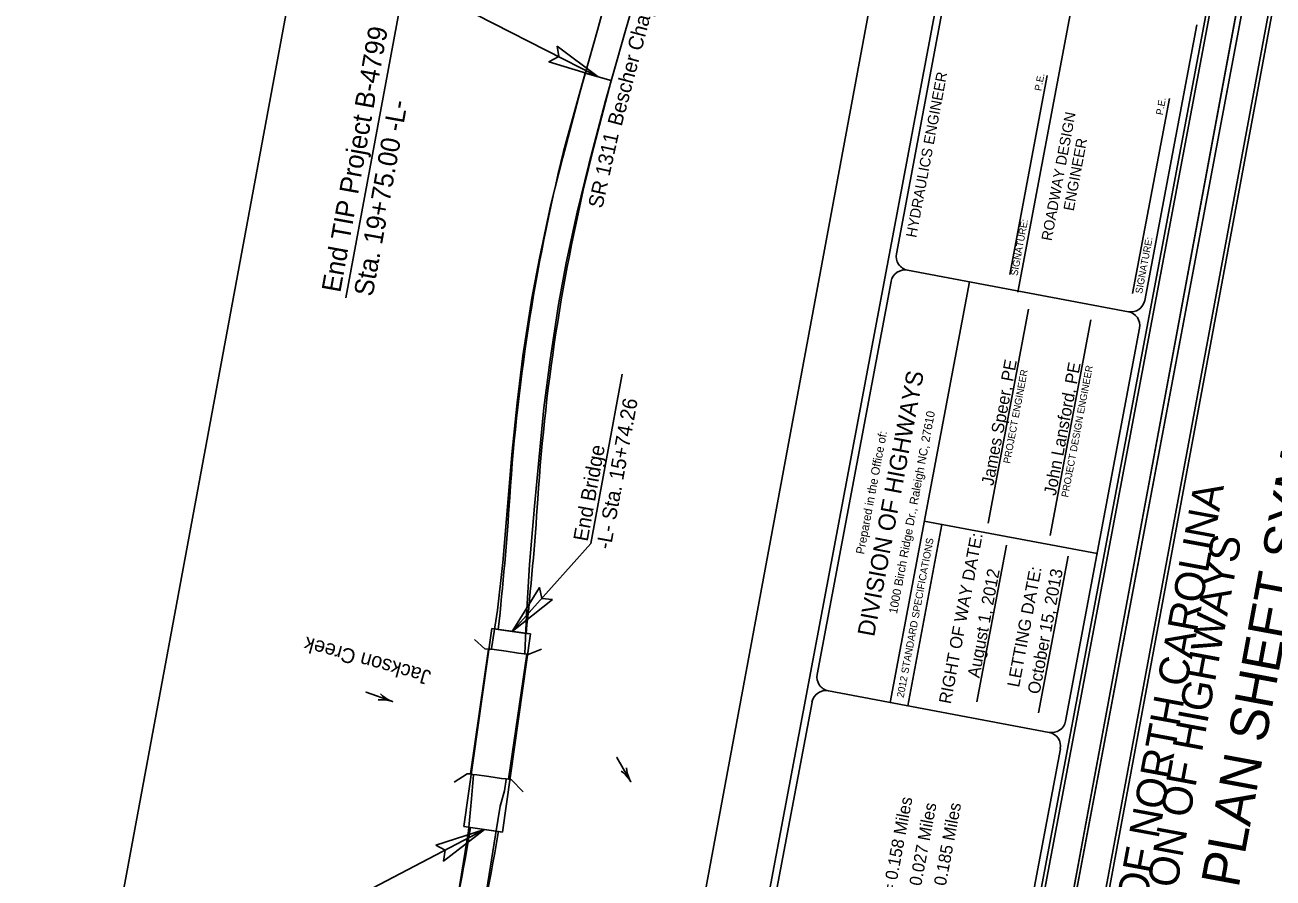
# Model space of a CAD drawing. Extents: x 1665923 to 1668724, y 690926 to 694920.
# Drawn here: x 1666413 to 1667302, y 691976 to 692584 of the extents above; entities that cross this region are included whole.
import ezdxf

# ---------------------------------------------------------------- set-up
doc = ezdxf.new("R2010")
doc.units = 0
for name, color, linetype in [('Default', 7, 'Continuous'), ('Prop Dimension Text', 7, 'Continuous'), ('Prop EOT', 7, 'Continuous'), ('Prop Horizontal Alignment Curve and Spiral Data', 7, 'Continuous'), ('Prop Roadway Bridge', 7, 'Continuous'), ('Prop Shade Light', 7, 'Continuous'), ('Prop Shade Medium', 7, 'Continuous'), ('Prop Terminator CELL', 7, 'Continuous'), ('Sheet Cutting Line CELL', 7, 'Continuous'), ('Sheet Data Field CELL', 7, 'Continuous'), ('Sheet Plot Border Inside CELL', 7, 'Continuous'), ('Sheet Plot Border Outside CELL', 7, 'Continuous'), ('Sheet Symbology CELL', 7, 'Continuous'), ('Sheet Title CELL', 7, 'Continuous')]:
    doc.layers.add(name, color=color, linetype=linetype)

msp = doc.modelspace()

# ---------------------------------------------------------------- linework, layer by layer
at = {"layer": 'Default'}
for p, q in [((1666415.46, 691603.54), (1666618.88, 692699.33)), ((1667019.7, 692624.93), (1666816.29, 691529.13)), ((1666665.28, 692105.04), (1666665.28, 692105.04)), ((1666839.45, 692053.18), (1666839.45, 692053.18))]:
    msp.add_line(p, q, dxfattribs=at)
for points in [[(1666871.81, 692766.65), (1666858.14, 692716.44), (1666844.61, 692667.79), (1666833.67, 692628.16), (1666820.6, 692580), (1666808.36, 692536.32), (1666795.94, 692489.34), (1666787.41, 692455.82), (1666779.4, 692417.44), (1666773.85, 692389.02), (1666767.56, 692347.94), (1666763.59, 692314.54), (1666759.71, 692277.72), (1666756.73, 692243.18), (1666753.15, 692200.75), (1666749.37, 692166.77), (1666745.14, 692139.52)], [(1666890.65, 692760.64), (1666876.96, 692710.6), (1666864.1, 692663.19), (1666852.75, 692621.99), (1666839.29, 692574.85), (1666826.38, 692529.73), (1666814.57, 692484.35), (1666806.17, 692450.25), (1666798.26, 692414.12), (1666792.93, 692384.55), (1666786.89, 692344.99), (1666782.51, 692310.9), (1666779.03, 692275.93), (1666775.87, 692240.77), (1666772.32, 692199.18), (1666770.12, 692163.28), (1666768.85, 692135.98)], [(1666742.95, 692139.06), (1666740.51, 692139.31), (1666732.99, 692145.93)], [(1666742.95, 692139.06), (1666730.34, 692050.04)], [(1666780.81, 692139.02), (1666771.3, 692135.29), (1666770.29, 692135.48), (1666768.56, 692135.61), (1666764.46, 692136.18), (1666755.73, 692137.56), (1666747.07, 692138.78), (1666744.15, 692138.93), (1666742.95, 692139.06)], [(1666757.34, 692046.27), (1666770.29, 692135.48)], [(1666666.06, 692107.19), (1666667.57, 692105.81), (1666669.21, 692104.54), (1666670.96, 692103.4), (1666672.79, 692102.41), (1666674.69, 692101.64), (1666655.88, 692108.44), (1666674.69, 692101.64), (1666672.73, 692102.27), (1666670.7, 692102.67), (1666668.62, 692102.91), (1666666.55, 692102.99), (1666664.51, 692102.89)], [(1666841.44, 692054.32), (1666841.7, 692052.29), (1666842.13, 692050.26), (1666842.73, 692048.25), (1666843.48, 692046.32), (1666844.44, 692044.51), (1666834.47, 692061.85), (1666844.44, 692044.51), (1666843.35, 692046.25), (1666842.06, 692047.87), (1666840.63, 692049.4), (1666839.1, 692050.79), (1666837.47, 692052.04)], [(1666732.26, 692049.55), (1666730.91, 692032.26), (1666728.79, 692009.64), (1666721.43, 691963.98), (1666714.02, 691926.14), (1666705.99, 691887.06), (1666697.47, 691850.95), (1666687.93, 691813.6), (1666676.04, 691773.22), (1666664.76, 691735.72), (1666650.35, 691694.65), (1666639.71, 691665.8), (1666622.52, 691626.38), (1666547.97, 691483.33)], [(1666759.41, 692045.97), (1666757.34, 692046.27), (1666755.6, 692046.54), (1666752.42, 692046.88), (1666743.3, 692048.3), (1666734.85, 692049.45), (1666731.69, 692049.79), (1666730.34, 692050.04), (1666727.98, 692050.17), (1666718.7, 692044.32)], [(1666755.68, 692046.05), (1666754.42, 692038.11), (1666751.48, 692027.16), (1666748.07, 692006.66), (1666740.59, 691960.63), (1666733.56, 691923.1), (1666725.06, 691881.58), (1666717.07, 691846.51), (1666706.93, 691807.61), (1666695.59, 691767.97), (1666683.55, 691729.45), (1666669.04, 691687.44), (1666658.04, 691658.5), (1666640.09, 691618.11), (1666566.69, 691473.24)], [(1666759.41, 692045.97), (1666767.74, 692037.29)]]:
    msp.add_lwpolyline(points, dxfattribs=at)
at = {"layer": 'Prop Dimension Text'}
for p, q in [((1666815.9, 692214.18), (1666838.32, 692334.97)), ((1666815.9, 692214.18), (1666759.9, 692151.64)), ((1666660.41, 691968.66), (1666740.2, 692010.47))]:
    msp.add_line(p, q, dxfattribs=at)
at = {"layer": 'Prop EOT'}
msp.add_line((1666812.02, 692549.38), (1666830.51, 692544.15), dxfattribs=at)
at = {"layer": 'Prop Horizontal Alignment Curve and Spiral Data'}
for p, q in [((1666641.53, 692389.21), (1666683.8, 692616.91)), ((1666683.8, 692616.91), (1666821.26, 692546.76))]:
    msp.add_line(p, q, dxfattribs=at)
at = {"layer": 'Prop Roadway Bridge'}
for p, q in [((1666725.47, 692012.56), (1666745.41, 692153.69)), ((1666745.41, 692153.69), (1666772.97, 692149.79)), ((1666753.03, 692008.66), (1666772.97, 692149.79)), ((1666725.47, 692012.56), (1666753.03, 692008.66))]:
    msp.add_line(p, q, dxfattribs=at)
at = {"layer": 'Prop Shade Light'}
for p, q in [((1666812.02, 692549.38), (1666798.53, 692501.27)), ((1666830.51, 692544.15), (1666812.02, 692549.38)), ((1666818.02, 692496.77), (1666830.51, 692544.15)), ((1666750.02, 692153.04), (1666769.8, 692150.24)), ((1666750.11, 692009.07), (1666730.35, 692011.87))]:
    msp.add_line(p, q, dxfattribs=at)
for centre, radius, start, end in [((1668165.11, 692154.06), 1410, 165.74431, 176.20848), ((1668165.11, 692154.06), 1390, 165.7259, 176.20849), ((1664481.09, 692397.24), 2282.04, 353.85705, 356.23256), ((1664473.21, 692398.72), 2310, 353.82477, 356.20849), ((1664481.09, 692397.24), 2282.04, 344.49766, 350.27786), ((1664473.21, 692398.72), 2310, 344.49666, 350.26654), ((1664473.21, 692398.72), 2310, 350.26654, 350.28892)]:
    msp.add_arc(centre, radius, start, end, dxfattribs=at)
at = {"layer": 'Prop Shade Medium'}
for p, q in [((1666745.41, 692153.69), (1666725.47, 692012.56)), ((1666750.02, 692153.04), (1666745.41, 692153.69)), ((1666753.03, 692008.66), (1666772.97, 692149.79)), ((1666725.47, 692012.56), (1666730.35, 692011.87)), ((1666730.35, 692011.87), (1666750.11, 692009.07)), ((1666750.11, 692009.07), (1666753.03, 692008.66))]:
    msp.add_line(p, q, dxfattribs=at)
msp.add_lwpolyline([(1666772.97, 692149.79), (1666769.8, 692150.24), (1666750.02, 692153.04)], dxfattribs=at)
at = {"layer": 'Prop Terminator CELL'}
for points in [[(1666792.02, 692568.65), (1666821.26, 692546.76), (1666786.11, 692557.52), (1666793.12, 692561.13)], [(1666788.53, 692174.32), (1666759.9, 692151.64), (1666779.28, 692182.88), (1666780.98, 692175.18)], [(1666705.44, 691999.26), (1666740.2, 692010.47), (1666711.11, 691988), (1666712.21, 691995.81)]]:
    msp.add_lwpolyline(points, close=True, dxfattribs=at)
at = {"layer": 'Sheet Cutting Line CELL'}
for p, q in [((1667310.99, 692782.59), (1667003.64, 691126.87)), ((1667003.64, 691126.87), (1667315.32, 692781.78))]:
    msp.add_line(p, q, dxfattribs=at)
at = {"layer": 'Sheet Plot Border Inside CELL'}
for points in [[(1666983.99, 691143.8), (1667292.44, 692781.51), (1666255.57, 692976.79), (1665947.12, 691339.09)], [(1668065.46, 690942.99), (1668369.62, 692581.5), (1667332.24, 692774.07), (1667028.08, 691135.56)]]:
    msp.add_lwpolyline(points, close=True, dxfattribs=at)
at = {"layer": 'Sheet Plot Border Outside CELL'}
for points in [[(1666234.34, 692985.37), (1665922.65, 691330.47), (1667003.64, 691126.87), (1667315.32, 692781.78)], [(1668085.16, 690926.11), (1668392.51, 692581.83), (1667310.99, 692782.59), (1667003.64, 691126.87)]]:
    msp.add_lwpolyline(points, close=True, dxfattribs=at)
at = {"layer": 'Sheet Symbology CELL'}
msp.add_lwpolyline([(1667332.46, 692761.31), (1667058.7, 691286.51), (1668090.06, 691095.06), (1668363.83, 692569.86)], close=True, dxfattribs=at)
at = {"layer": 'Sheet Title CELL'}
for p, q in [((1666835.29, 691394.66), (1667098.11, 692790.12)), ((1667033.62, 692420.68), (1667070.6, 692617)), ((1667120.02, 692393.31), (1667160.87, 692610.17)), ((1667114.29, 692405.99), (1667140.98, 692547.75)), ((1667201.83, 692392.31), (1667228.03, 692531.36)), ((1667198.85, 692379.38), (1667041.61, 692409)), ((1666977.17, 692120.95), (1667029.92, 692401.02)), ((1667085.59, 692400.72), (1667029.12, 692100.99)), ((1667098.97, 692228.72), (1667127.7, 692381.18)), ((1667143.13, 692220.04), (1667172.05, 692373.59)), ((1667066.01, 692227.9), (1667041.65, 692098.63)), ((1667053.47, 692230.26), (1667176.56, 692207.08)), ((1667111.91, 692213.15), (1667090.86, 692101.37)), ((1667155.82, 692205.29), (1667134.76, 692093.51)), ((1667058.99, 692190.66), (1667058.99, 692190.66)), ((1667101.39, 692157.23), (1667101.39, 692157.23)), ((1666985.15, 692109.27), (1667142.38, 692079.66)), ((1666903.15, 691727.86), (1666973.48, 692101.29))]:
    msp.add_line(p, q, dxfattribs=at)
for points in [[(1667011.84, 691305.44), (1667285.77, 692759.87)], [(1667210.51, 692387.36), (1667247.49, 692583.69)], [(1667154.06, 692087.63), (1667206.82, 692367.71)], [(1667080.04, 691694.54), (1667150.37, 692067.98)]]:
    msp.add_lwpolyline(points, dxfattribs=at)
for centre, start, end in [((1667043.4, 692418.84), 169.33381, 259.33381), ((1667039.7, 692399.19), 79.33381, 169.33381), ((1667200.64, 692389.23), 259.33381, 349.33381), ((1667196.94, 692369.57), 349.33381, 79.33381), ((1666986.95, 692119.11), 169.33381, 259.33381), ((1666983.25, 692099.45), 79.33381, 169.33381), ((1667144.19, 692089.5), 259.33381, 349.33381), ((1667140.49, 692069.84), 349.33381, 79.33381)]:
    msp.add_arc(centre, 10, start, end, dxfattribs=at)

# ---------------------------------------------------------------- texts
at = {"layer": 'Prop Dimension Text'}
for s, rotation, p in [('Bescher Chapel Rd.', 75.2455, (1666837.81, 692511.02)), ('SR 1311', 77.46946, (1666824.11, 692452.55)), ('-L- Sta. 15+74.26', 79.7152, (1666830.01, 692209.61)), ('End Bridge', 79.7152, (1666813.66, 692215.26)), ('Jackson Creek', 164.63922, (1666702.88, 692123.33))]:
    msp.add_text(s, height=10.5, rotation=rotation, dxfattribs=at).set_placement(p)
at = {"layer": 'Prop Horizontal Alignment Curve and Spiral Data'}
for s, p in [('End TIP Project B-4799', (1666637.49, 692392.53)), ('Sta. 19+75.00 -L-', (1666660.49, 692389.69))]:
    msp.add_text(s, height=13.65, rotation=79.79927, dxfattribs=at).set_placement(p)
at = {"layer": 'Sheet Data Field CELL'}
for s, height, p in [('James Speer, PE             ', 8.7501, (1667102.61, 692255.01)), ('John Lansford, PE           ', 8.7501, (1667147.08, 692247.94)), ('August 1, 2012 ', 8.7501, (1667092.7, 692118.01)), ('October 15, 2013', 8.7501, (1667135.49, 692106.47)), ('Length Roadway TIP Project B-4799 = 0.158 Miles', 8.75, (1666996.42, 691774.34)), ('Length Bridge TIP Project B-4799 = 0.027 Miles', 8.75, (1667016.34, 691784.86)), ('Total Length TIP Project B-4799 = 0.185 Miles', 8.75, (1667035.34, 691792.57))]:
    msp.add_text(s, height=height, rotation=79.33381, dxfattribs=at).set_placement(p)
at = {"layer": 'Sheet Symbology CELL'}
for s, height, p in [('CONVENTIONAL  PLAN SHEET SYMBOLS', 27.2003, (1667221.18, 691666.22)), ('STATE OF NORTH CAROLINA', 21.419, (1667193.19, 691857.86)), ('DIVISION OF HIGHWAYS', 21.419, (1667218.04, 691886.65))]:
    msp.add_text(s, height=height, rotation=79.48395, dxfattribs=at).set_placement(p)
at = {"layer": 'Sheet Title CELL'}
for s, height, p in [(' HYDRAULICS ENGINEER', 7.5, (1667047.16, 692429.02)), ('P.E.', 5, (1667136.76, 692536.37)), ('P.E.', 5, (1667223.28, 692519.18)), ('ROADWAY DESIGN', 7.4994, (1667144.11, 692429.48)), ('ENGINEER', 7.499, (1667159.82, 692450.79)), ('SIGNATURE:', 5, (1667119.83, 692404.67)), ('SIGNATURE:', 5, (1667208.58, 692391.95)), ('PROJECT DESIGN ENGINEER', 4.9995, (1667155.87, 692246.85)), ('DIVISION OF HIGHWAYS', 12.1872, (1667017.71, 692147.39)), ('PROJECT ENGINEER', 4.9995, (1667114.55, 692270.91)), ('1000 Birch Ridge Dr., Raleigh NC, 27610', 6, (1667033.99, 692163.83)), ('Prepared in the Office of:', 5.9994, (1667010.5, 692206.25)), ('2012 STANDARD SPECIFICATIONS', 5.2, (1667038.77, 692104.1)), ('RIGHT OF WAY DATE: ', 8.7498, (1667072.3, 692099.52)), ('LETTING DATE:', 8.7498, (1667120.98, 692111.36))]:
    msp.add_text(s, height=height, rotation=79.33381, dxfattribs=at).set_placement(p)

doc.saveas('drawing.dxf')
